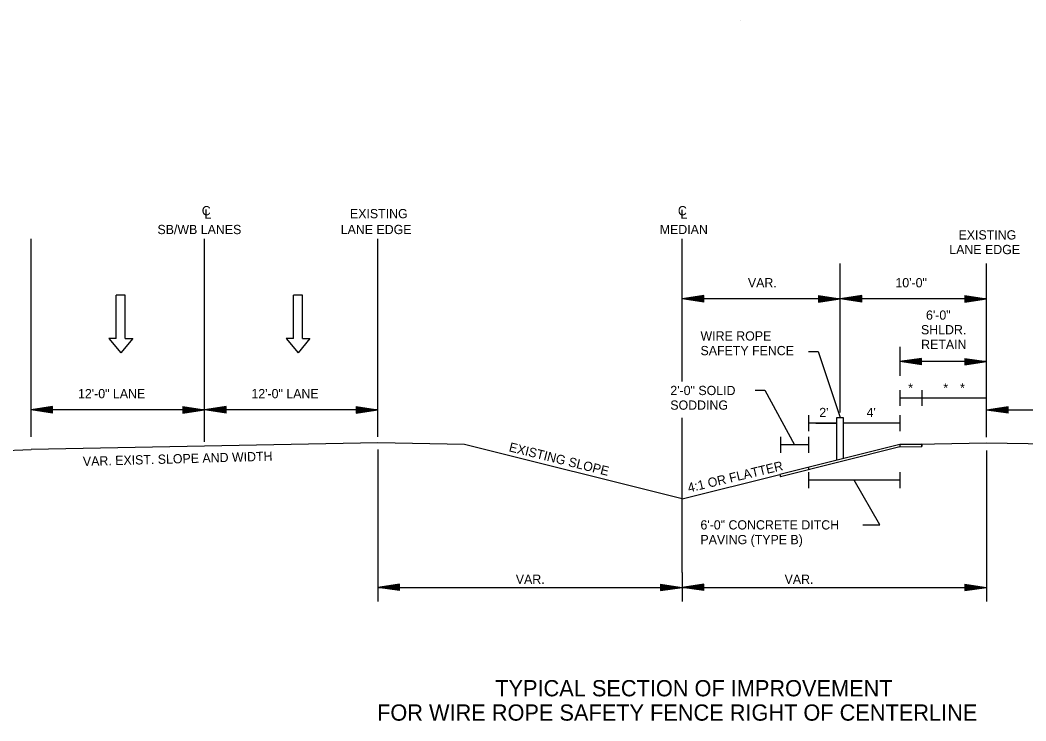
# Model space of a CAD drawing. Extents: x 1641422 to 1649187, y 577497 to 580642.
# Drawn here: x 1645133 to 1646438, y 579732 to 580642 of the extents above; entities that cross this region are included whole.
import ezdxf

# ---------------------------------------------------------------- set-up
doc = ezdxf.new("R2010")
doc.units = 0
for name, color, linetype in [('Default', 7, 'Continuous'), ('R_Border', 7, 'Continuous'), ('R_Draft', 7, 'Continuous')]:
    doc.layers.add(name, color=color, linetype=linetype)

msp = doc.modelspace()

# ---------------------------------------------------------------- linework, layer by layer
at = {"layer": 'Default'}
for p, q in [((1646192.6, 580125.4), (1646200.7, 580125.4)), ((1646192.6, 580070.2), (1646192.6, 580125.4)), ((1646200.7, 580125.4), (1646200.7, 580072.3)), ((1646200.7, 580122.4), (1646200.7, 580115.2)), ((1646192.6, 580118.2), (1646155.9, 580118.2)), ((1646165.4, 580118.2), (1646189.8, 580118.2)), ((1646168.2, 580118.2), (1646192.6, 580118.2)), ((1646274.2, 580118.2), (1646200.7, 580118.2)), ((1645991.7, 580020), (1645709.3, 580090.6)), ((1646274.2, 580090.6), (1646118.4, 580051.7)), ((1646155.9, 580090.2), (1646119.2, 580090.2)), ((1646274.2, 580087.4), (1646119.2, 580048.7)), ((1646274.2, 580090.6), (1646302.7, 580091.2)), ((1646274.2, 580090.6), (1646274.2, 580087.4)), ((1646302.7, 580091.2), (1646302.7, 580088)), ((1645991.7, 580020), (1646118.4, 580051.7)), ((1646118.4, 580051.7), (1646119.2, 580048.7))]:
    msp.add_line(p, q, dxfattribs=at)
msp.add_lwpolyline([(1646274.2, 580087.4), (1646302.7, 580088), (1646302.7, 580091.2), (1646274.2, 580090.6)], close=True, dxfattribs=at)
at = {"layer": 'R_Border'}
msp.add_line((1646067.8, 580641.6), (1646067.8, 580641.6), dxfattribs=at)
msp.add_line((1646067.8, 580641.6), (1646067.8, 580641.6), dxfattribs=at)
at = {"layer": 'R_Draft'}
for p, q in [((1645146.8, 580100.3), (1645146.8, 580357.7)), ((1645371.8, 580093.9), (1645371.8, 580357.7)), ((1645596.8, 580100.3), (1645596.8, 580357.7)), ((1645991.7, 580172.4), (1645991.7, 580357.7)), ((1646196.7, 580132.2), (1646196.7, 580325.7)), ((1646386.7, 580100), (1646386.7, 580325.7)), ((1645269.2, 580284.4), (1645257.5, 580284.4)), ((1645257.5, 580228.3), (1645257.5, 580284.4)), ((1645269.2, 580228.3), (1645269.2, 580284.4)), ((1645499.2, 580284.4), (1645487.5, 580284.4)), ((1645487.5, 580228.3), (1645487.5, 580284.4)), ((1645499.2, 580228.3), (1645499.2, 580284.4)), ((1646019.8, 580283.9), (1645991.7, 580279.7)), ((1646019.8, 580275.5), (1645991.7, 580279.7)), ((1646196.7, 580279.7), (1645991.7, 580279.7)), ((1646019.8, 580283.2), (1645996.4, 580279.7)), ((1646019.8, 580276.2), (1645996.4, 580279.7)), ((1646019.8, 580282.5), (1646001.3, 580279.7)), ((1646019.8, 580276.9), (1646001.3, 580279.7)), ((1646019.8, 580281.8), (1646005.9, 580279.7)), ((1646019.8, 580277.6), (1646005.9, 580279.7)), ((1646019.8, 580281), (1646010.7, 580279.7)), ((1646019.8, 580278.3), (1646010.7, 580279.7)), ((1646019.8, 580280.3), (1646015.4, 580279.7)), ((1646019.8, 580279), (1646015.4, 580279.7)), ((1646019.8, 580275.5), (1646019.8, 580283.9)), ((1646168.6, 580283.9), (1646196.7, 580279.7)), ((1646168.6, 580283.9), (1646168.6, 580275.5)), ((1646168.6, 580283.2), (1646192, 580279.7)), ((1646168.6, 580282.5), (1646187.1, 580279.7)), ((1646168.6, 580281.8), (1646182.5, 580279.7)), ((1646168.6, 580281), (1646177.7, 580279.7)), ((1646168.6, 580280.3), (1646173, 580279.7)), ((1646168.6, 580275.5), (1646196.7, 580279.7)), ((1646168.6, 580278.3), (1646177.7, 580279.7)), ((1646168.6, 580276.9), (1646187.1, 580279.7)), ((1646168.6, 580276.2), (1646192, 580279.7)), ((1646168.6, 580277.6), (1646182.5, 580279.7)), ((1646168.6, 580279), (1646173, 580279.7)), ((1646224.8, 580283.9), (1646196.7, 580279.7)), ((1646224.8, 580275.5), (1646196.7, 580279.7)), ((1646386.7, 580279.7), (1646199.2, 580279.7)), ((1646224.8, 580283.2), (1646201.4, 580279.7)), ((1646224.8, 580276.2), (1646201.4, 580279.7)), ((1646224.8, 580282.5), (1646206.2, 580279.7)), ((1646224.8, 580276.9), (1646206.2, 580279.7)), ((1646224.8, 580281.8), (1646210.9, 580279.7)), ((1646224.8, 580277.6), (1646210.9, 580279.7)), ((1646224.8, 580281), (1646215.7, 580279.7)), ((1646224.8, 580278.3), (1646215.7, 580279.7)), ((1646224.8, 580280.3), (1646220.4, 580279.7)), ((1646224.8, 580279), (1646220.4, 580279.7)), ((1646224.8, 580275.5), (1646224.8, 580283.9)), ((1646358.6, 580283.9), (1646386.7, 580279.7)), ((1646358.6, 580283.9), (1646358.6, 580275.5)), ((1646358.6, 580283.2), (1646382, 580279.7)), ((1646358.6, 580282.5), (1646377.1, 580279.7)), ((1646358.6, 580281.8), (1646372.5, 580279.7)), ((1646358.6, 580281), (1646367.7, 580279.7)), ((1646358.6, 580280.3), (1646363, 580279.7)), ((1646358.6, 580275.5), (1646386.7, 580279.7)), ((1646358.6, 580278.3), (1646367.7, 580279.7)), ((1646358.6, 580276.9), (1646377.1, 580279.7)), ((1646358.6, 580276.2), (1646382, 580279.7)), ((1646358.6, 580277.6), (1646372.5, 580279.7)), ((1646358.6, 580279), (1646363, 580279.7)), ((1646274.2, 580217.4), (1646274.2, 580179.9)), ((1646302.3, 580202.4), (1646274.2, 580198.1)), ((1646302.3, 580201.7), (1646278.9, 580198.1)), ((1646302.3, 580200.9), (1646283.7, 580198.1)), ((1646302.3, 580193.9), (1646302.3, 580202.4)), ((1646358.6, 580202.4), (1646386.7, 580198.1)), ((1646358.6, 580202.4), (1646358.6, 580193.9)), ((1646358.6, 580201.7), (1646382, 580198.1)), ((1646358.6, 580200.9), (1646377.1, 580198.1)), ((1646386.7, 580198.1), (1646274.2, 580198.1)), ((1646302.3, 580193.9), (1646274.2, 580198.1)), ((1646302.3, 580194.6), (1646278.9, 580198.1)), ((1646302.3, 580195.4), (1646283.7, 580198.1)), ((1646302.3, 580200.2), (1646288.4, 580198.1)), ((1646302.3, 580196.1), (1646288.4, 580198.1)), ((1646302.3, 580199.5), (1646293.2, 580198.1)), ((1646302.3, 580196.8), (1646293.2, 580198.1)), ((1646302.3, 580198.8), (1646297.9, 580198.1)), ((1646302.3, 580197.5), (1646297.9, 580198.1)), ((1646358.6, 580200.2), (1646372.5, 580198.1)), ((1646358.6, 580199.5), (1646367.7, 580198.1)), ((1646358.6, 580198.8), (1646363, 580198.1)), ((1646358.6, 580193.9), (1646386.7, 580198.1)), ((1646358.6, 580196.8), (1646367.7, 580198.1)), ((1646358.6, 580195.4), (1646377.1, 580198.1)), ((1646358.6, 580194.6), (1646382, 580198.1)), ((1646358.6, 580196.1), (1646372.5, 580198.1)), ((1646358.6, 580197.5), (1646363, 580198.1)), ((1645146.8, 580100.6), (1645146.8, 580154.2)), ((1646274.2, 580161.3), (1646274.2, 580140.7)), ((1646274.2, 580151), (1646302.6, 580151)), ((1646302.6, 580161.3), (1646302.6, 580140.7)), ((1646302.6, 580151), (1646386.7, 580151)), ((1645174.9, 580139.8), (1645146.8, 580135.6)), ((1645371.8, 580135.6), (1645146.8, 580135.6)), ((1645174.9, 580131.4), (1645146.8, 580135.6)), ((1645174.9, 580139.1), (1645151.5, 580135.6)), ((1645174.9, 580132.1), (1645151.5, 580135.6)), ((1645174.9, 580138.4), (1645156.3, 580135.6)), ((1645174.9, 580132.8), (1645156.3, 580135.6)), ((1645174.9, 580137.7), (1645161, 580135.6)), ((1645174.9, 580133.5), (1645161, 580135.6)), ((1645174.9, 580137), (1645165.8, 580135.6)), ((1645174.9, 580134.3), (1645165.8, 580135.6)), ((1645174.9, 580136.3), (1645170.5, 580135.6)), ((1645174.9, 580135), (1645170.5, 580135.6)), ((1645174.9, 580131.4), (1645174.9, 580139.8)), ((1645343.7, 580139.8), (1645371.8, 580135.6)), ((1645343.7, 580139.8), (1645343.7, 580131.4)), ((1645343.7, 580139.1), (1645367.1, 580135.6)), ((1645343.7, 580138.4), (1645362.3, 580135.6)), ((1645343.7, 580137.7), (1645357.6, 580135.6)), ((1645343.7, 580137), (1645352.8, 580135.6)), ((1645343.7, 580136.3), (1645348.1, 580135.6)), ((1645343.7, 580131.4), (1645371.8, 580135.6)), ((1645343.7, 580134.3), (1645352.8, 580135.6)), ((1645343.7, 580132.8), (1645362.3, 580135.6)), ((1645343.7, 580132.1), (1645367.1, 580135.6)), ((1645343.7, 580133.5), (1645357.6, 580135.6)), ((1645343.7, 580135), (1645348.1, 580135.6)), ((1645399.9, 580139.8), (1645371.8, 580135.6)), ((1645596.8, 580135.6), (1645371.8, 580135.6)), ((1645399.9, 580131.4), (1645371.8, 580135.6)), ((1645399.9, 580139.1), (1645376.5, 580135.6)), ((1645399.9, 580132.1), (1645376.5, 580135.6)), ((1645399.9, 580138.4), (1645381.3, 580135.6)), ((1645399.9, 580132.8), (1645381.3, 580135.6)), ((1645399.9, 580137.7), (1645386, 580135.6)), ((1645399.9, 580133.5), (1645386, 580135.6)), ((1645399.9, 580137), (1645390.8, 580135.6)), ((1645399.9, 580134.3), (1645390.8, 580135.6)), ((1645399.9, 580136.3), (1645395.5, 580135.6)), ((1645399.9, 580135), (1645395.5, 580135.6)), ((1645399.9, 580131.4), (1645399.9, 580139.8)), ((1645568.6, 580139.8), (1645596.8, 580135.6)), ((1645568.6, 580139.8), (1645568.6, 580131.4)), ((1645568.6, 580139.1), (1645592.1, 580135.6)), ((1645568.6, 580138.4), (1645587.2, 580135.6)), ((1645568.6, 580137.7), (1645582.6, 580135.6)), ((1645568.6, 580137), (1645577.8, 580135.6)), ((1645568.6, 580136.3), (1645573.1, 580135.6)), ((1645568.6, 580131.4), (1645596.8, 580135.6)), ((1645568.6, 580134.3), (1645577.8, 580135.6)), ((1645568.6, 580132.8), (1645587.2, 580135.6)), ((1645568.6, 580132.1), (1645592.1, 580135.6)), ((1645568.6, 580133.5), (1645582.6, 580135.6)), ((1645568.6, 580135), (1645573.1, 580135.6)), ((1646611.6, 580135.3), (1646386.6, 580135.3)), ((1646414.8, 580139.5), (1646386.7, 580135.3)), ((1646414.8, 580131.1), (1646386.7, 580135.3)), ((1646414.8, 580138.8), (1646391.4, 580135.3)), ((1646414.8, 580131.8), (1646391.4, 580135.3)), ((1646414.8, 580138.1), (1646396.2, 580135.3)), ((1646414.8, 580132.5), (1646396.2, 580135.3)), ((1646414.8, 580137.4), (1646400.9, 580135.3)), ((1646414.8, 580133.2), (1646400.9, 580135.3)), ((1646414.8, 580136.7), (1646405.7, 580135.3)), ((1646414.8, 580133.9), (1646405.7, 580135.3)), ((1646414.8, 580136), (1646410.4, 580135.3)), ((1646414.8, 580134.6), (1646410.4, 580135.3)), ((1646414.8, 580131.1), (1646414.8, 580139.5)), ((1645991.7, 579924.3), (1645991.7, 580125)), ((1646155.9, 580128.5), (1646155.9, 580107.9)), ((1646274.2, 580128.5), (1646274.2, 580107.9)), ((1646119.2, 580100.5), (1646119.2, 580079.9)), ((1646155.9, 580100.5), (1646155.9, 580079.9)), ((1644996.3, 580077.8), (1645146.8, 580083.9)), ((1645371.8, 580088.4), (1645146.8, 580083.9)), ((1645596.8, 580092.9), (1645371.8, 580088.4)), ((1645709.3, 580090.6), (1645596.8, 580092.9)), ((1645596.8, 580083.9), (1645596.8, 579886.8)), ((1646274.2, 580090.6), (1646386.7, 580092.9)), ((1646386.7, 580092.9), (1646611.6, 580088.4)), ((1646386.7, 580082.9), (1646386.7, 579886.8)), ((1646155.9, 580061), (1646155.9, 580057.9)), ((1646155.9, 580054.6), (1646155.9, 580034)), ((1646274.2, 580044.3), (1646155.9, 580044.3)), ((1646274.2, 580054.6), (1646274.2, 580034)), ((1645991.7, 579924.3), (1645991.7, 579886.8)), ((1645624.9, 579909.3), (1645596.8, 579905.1)), ((1645596.8, 579905.1), (1645991.7, 579905.1)), ((1645624.9, 579900.8), (1645596.8, 579905.1)), ((1645624.9, 579908.6), (1645601.5, 579905.1)), ((1645624.9, 579901.5), (1645601.5, 579905.1)), ((1645624.9, 579907.9), (1645606.3, 579905.1)), ((1645624.9, 579902.3), (1645606.3, 579905.1)), ((1645624.9, 579907.1), (1645611, 579905.1)), ((1645624.9, 579903), (1645611, 579905.1)), ((1645624.9, 579906.4), (1645615.8, 579905.1)), ((1645624.9, 579903.7), (1645615.8, 579905.1)), ((1645624.9, 579905.7), (1645620.4, 579905.1)), ((1645624.9, 579904.4), (1645620.4, 579905.1)), ((1645624.9, 579900.8), (1645624.9, 579909.3)), ((1645963.6, 579909.3), (1645991.7, 579905.1)), ((1645963.6, 579909.3), (1645963.6, 579900.8)), ((1645963.6, 579908.6), (1645987, 579905.1)), ((1645963.6, 579907.9), (1645982.2, 579905.1)), ((1645963.6, 579907.1), (1645977.5, 579905.1)), ((1645963.6, 579906.4), (1645972.7, 579905.1)), ((1645963.6, 579905.7), (1645968, 579905.1)), ((1645963.6, 579900.8), (1645991.7, 579905.1)), ((1645963.6, 579903.7), (1645972.7, 579905.1)), ((1645963.6, 579902.3), (1645982.2, 579905.1)), ((1645963.6, 579901.5), (1645987, 579905.1)), ((1645963.6, 579903), (1645977.5, 579905.1)), ((1645963.6, 579904.4), (1645968, 579905.1)), ((1645963.6, 579905.1), (1645991.7, 579905.1)), ((1646019.8, 579909.3), (1645991.7, 579905.1)), ((1645991.7, 579905.1), (1646386.7, 579905.1)), ((1646019.8, 579900.8), (1645991.7, 579905.1)), ((1646019.8, 579908.6), (1645996.4, 579905.1)), ((1646019.8, 579901.5), (1645996.4, 579905.1)), ((1646019.8, 579907.9), (1646001.3, 579905.1)), ((1646019.8, 579902.3), (1646001.3, 579905.1)), ((1646019.8, 579907.1), (1646005.9, 579905.1)), ((1646019.8, 579903), (1646005.9, 579905.1)), ((1646019.8, 579906.4), (1646010.7, 579905.1)), ((1646019.8, 579903.7), (1646010.7, 579905.1)), ((1646019.8, 579905.7), (1646015.4, 579905.1)), ((1646019.8, 579904.4), (1646015.4, 579905.1)), ((1646019.8, 579900.8), (1646019.8, 579909.3)), ((1646246.1, 579905.1), (1646274.2, 579905.1)), ((1646358.6, 579909.3), (1646386.7, 579905.1)), ((1646358.6, 579909.3), (1646358.6, 579900.8)), ((1646358.6, 579908.6), (1646382, 579905.1)), ((1646358.6, 579907.9), (1646377.1, 579905.1)), ((1646358.6, 579907.1), (1646372.5, 579905.1)), ((1646358.6, 579906.4), (1646367.7, 579905.1)), ((1646358.6, 579905.7), (1646363, 579905.1)), ((1646358.6, 579900.8), (1646386.7, 579905.1)), ((1646358.6, 579903.7), (1646367.7, 579905.1)), ((1646358.6, 579902.3), (1646377.1, 579905.1)), ((1646358.6, 579901.5), (1646382, 579905.1)), ((1646358.6, 579903), (1646372.5, 579905.1)), ((1646358.6, 579904.4), (1646363, 579905.1))]:
    msp.add_line(p, q, dxfattribs=at)
for points in [[(1645257.5, 580228.3), (1645247.9, 580228.3), (1645263.4, 580209.5)], [(1645269.2, 580228.3), (1645278.8, 580228.3), (1645263.4, 580209.5)], [(1645487.5, 580228.3), (1645477.9, 580228.3), (1645493.4, 580209.5)], [(1645499.2, 580228.3), (1645508.8, 580228.3), (1645493.4, 580209.5)], [(1646155.8, 580211.4), (1646168.1, 580211.4), (1646196.7, 580125.4)], [(1646086.7, 580160.9), (1646099.1, 580160.9), (1646137.5, 580090.2)], [(1646226.4, 579986.2), (1646248.3, 579986.2), (1646215, 580044.3)]]:
    msp.add_lwpolyline(points, dxfattribs=at)

# ---------------------------------------------------------------- texts
at = {"layer": 'Default'}
for s, p in [('*', (1646285.1, 580158)), ('*', (1646330.7, 580158)), ('*', (1646352.4, 580158)), ("2'", (1646169.7, 580126.1)), ("4'", (1646231.1, 580126.1))]:
    msp.add_text(s, height=12, dxfattribs=at).set_placement(p)
at = {"layer": 'R_Draft'}
for s, height, p in [('C', 12, (1645368.4, 580388.1)), ('EXISTING', 12, (1645560.7, 580384.3)), ('C', 12, (1645986.2, 580388.1)), ('L', 12, (1645371.8, 580383.7)), ('L', 12, (1645989.6, 580383.6)), ('SB/WB LANES', 12, (1645310.9, 580363.7)), ('LANE EDGE', 12, (1645548.7, 580363.7)), ('MEDIAN', 12, (1645962.7, 580363.7)), ('EXISTING', 12, (1646350.4, 580356.7)), ('LANE EDGE', 12, (1646338.4, 580337.7)), ('VAR.', 12, (1646077.1, 580294.6)), ('10\'-0"', 12, (1646268.5, 580294.6)), ('6\'-0"', 12, (1646308.2, 580252.6)), ('SHLDR.', 12, (1646301.7, 580233.6)), ('WIRE ROPE', 12, (1646015.6, 580225.5)), ('SAFETY FENCE', 12, (1646015.6, 580206.5)), ('RETAIN', 12, (1646301.9, 580214.5)), ('12\'-0" LANE', 12, (1645207.8, 580150.6)), ('12\'-0" LANE', 12, (1645432.8, 580150.6)), ('2\'-0" SOLID', 12, (1645976.4, 580154.7)), ('SODDING', 12, (1645976.4, 580135.7)), ('6\'-0" CONCRETE DITCH', 12, (1646015.5, 579980.2)), ('PAVING (TYPE B)', 12, (1646015.5, 579961.1)), ('VAR.', 12, (1645775.9, 579909.6)), ('VAR.', 12, (1646124.7, 579909.6)), ('TYPICAL SECTION OF IMPROVEMENT', 21.094, (1645749.2, 579763.6)), ('FOR WIRE ROPE SAFETY FENCE RIGHT OF CENTERLINE', 21.094, (1645595.9, 579732))]:
    msp.add_text(s, height=height, dxfattribs=at).set_placement(p)
for s, rotation, p in [('EXISTING SLOPE', 345.997, (1645766.2, 580081.9)), ('VAR. EXIST. SLOPE AND WIDTH', 1.6096, (1645214.3, 580062.6)), ('4:1 OR FLATTER', 13.4085, (1646000.5, 580028.2))]:
    msp.add_text(s, height=12, rotation=rotation, dxfattribs=at).set_placement(p)

doc.saveas('drawing.dxf')
